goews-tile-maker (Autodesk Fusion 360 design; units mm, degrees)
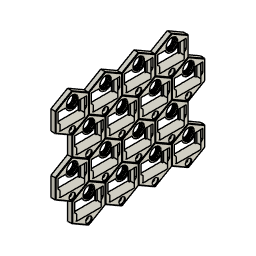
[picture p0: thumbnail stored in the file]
parameter "width" = 42
parameter "height" = 48.497
parameter "offset" = 36.373
parameter "DoubleVerticalDistance" = 72.746
sketch "Reference" plane through (0, 0, 0) normal (1, 0, 0) x axis (0, 1, 0)
  line L1 (-18, -1.6244) -> (-15.5, -4.1244)
  line L2 (-18, 9.8756) -> (-18, -1.6244)
  line L3 (-8.5448, 9.8756) -> (-18, 9.8756)
  line L4 (18, 9.8756) -> (8.5448, 9.8756)
  line L5 (18, -1.6244) -> (18, 9.8756)
  line L6 (15.5, -4.1244) -> (18, -1.6244)
  line L7 (15.5, -12.1244) -> (15.5, -4.1244)
  line L8 (-15.5, -12.1244) -> (15.5, -12.1244)
  line L9 (-15.5, -4.1244) -> (-15.5, -12.1244)
  line L10 (20.5, 11.8357) -> (20.5, -11.8357)
  line L11 (0, 23.6714) -> (20.5, 11.8357)
  line L12 (-20.5, 11.8357) -> (0, 23.6714)
  line L13 (-20.5, -11.8357) -> (-20.5, 11.8357)
  line L14 (0, -23.6714) -> (-20.5, -11.8357)
  line L15 (20.5, -11.8357) -> (0, -23.6714)
  circle C1 centre (0, 12.7017) radius 7.1612
  arc A1 centre (0, 12.7017) radius 9 clockwise from (8.5448, 9.8756) to (-8.5448, 9.8756)
  circle C2 centre (0, -18.2487) radius 4
  point P22 (-42, 24.2487)
  point P27 (-21, -12.1244)
  point P20 (0, -24.2487)
  point P23 (-21, 60.6218)
  point P21 (21, -12.1244)
  point P25 (0, 48.4974)
  point P28 (0, 24.2487)
  point P26 (21, 12.1244)
  dimension "d7" distance P22 P27 = 36.3731
  dimension "d8" distance P20 P23 = 84.8705
  dimension "d9" distance P21 P23 = 84
  dimension "d10" distance P21 P22 = 63
  dimension "d11" distance P20 P25 = 72.7461
  dimension "d17" distance P21 P27 = 42
  dimension "d18" distance P20 P28 = 48.4974
  dimension "d19" distance P23 P28 = 36.3731
  dimension "d24" distance P20 P26 = 36.3731
copy_paste_bodies "CutPasteBodies"
sketch "patch" plane through (-6, 0, 0) normal (-1, 0, 0) x axis (0, -1, 0)
  line L1 (3, 25.9808) -> (16.0118, 18.4684)
  line L2 (3, 26.0061) -> (3, 25.9808)
  line L3 (39, 26.0061) -> (3, 26.0061)
  line L4 (39, 25.9808) -> (39, 26.0061)
  line L5 (25.9882, 18.4684) -> (39, 25.9808)
  curve K1 (16.3334, 53.0977) -> (19.1178, 42.0472)
  curve K2 (22.8822, 42.0472) -> (25.6666, 53.0977)
  line L6 (0, 24.2487) -> (0, 48.4974)
  line L7 (21, 12.1244) -> (0, 24.2487)
  line L8 (42, 24.2487) -> (21, 12.1244)
  line L9 (42, 48.4974) -> (42, 24.2487)
  line L10 (21, 60.6218) -> (42, 48.4974)
  line L11 (0, 48.4974) -> (21, 60.6218)
  line L12 (7.5, 46.2487) -> (7.5, 30.2487)
  line L13 (12.4552, 46.2487) -> (7.5, 46.2487)
  line L14 (34.5, 46.2487) -> (29.5448, 46.2487)
  line L15 (34.5, 30.2487) -> (34.5, 46.2487)
  line L16 (7.5, 30.2487) -> (34.5, 30.2487)
  line L17 (9.8586, 52.0614) -> (11.841, 52.0614)
  line L18 (9.8586, 48.8529) -> (9.8586, 52.0614)
  line L19 (11.841, 48.8529) -> (9.8586, 48.8529)
  line L20 (11.841, 52.0614) -> (11.841, 48.8529)
  line L21 (32.2218, 52.0614) -> (29.7148, 52.0614)
  line L22 (32.2218, 48.4173) -> (32.2218, 52.0614)
  line L23 (29.7148, 48.4173) -> (32.2218, 48.4173)
  line L24 (29.7148, 52.0614) -> (29.7148, 48.4173)
  arc A1 centre (21, 18.1244) radius 5 clockwise from (16.0118, 18.4684) to (25.9882, 18.4684)
  arc A2 centre (21, 49.0748) radius 6.1612 clockwise from (16.3334, 53.0977) to (25.6666, 53.0977)
  arc A3 centre (21, 49.0748) radius 7.2753 clockwise from (22.8822, 42.0472) to (19.1178, 42.0472)
  circle C1 centre (21, 18.1244) radius 2
  arc A4 centre (21, 49.0748) radius 9 clockwise from (29.5448, 46.2487) to (12.4552, 46.2487)
  horizontal L17
  vertical L18
  horizontal L19
  vertical L20
  horizontal L21
  vertical L22
  horizontal L23
  vertical L24
extrude "Extrude1" add sketch "patch" profile of L17 L18 L19 L20 L21 L22 L23 L24 against normal blind 6
copy_paste_bodies "CopyPasteBodies3"
copy_paste_bodies "CopyPasteBodies4"
move "Move3"
align "Align1"
move "Move2"
combine "Combine3" bodies "Hex (1)"
rectangular_pattern "R-Pattern3" countU 2 (= "VerticalQTY / 2") uSpaceDistance 72.746 vSpaceDistance -42 bodies "Hex (1)", "Hex (8)", "Hex (2)", "Hex (3)", "Hex (4)", "Hex (5)", "Hex (6)"
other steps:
base_feature "Base Feature1" bodies "Hex"
base_feature "Base Feature3" bodies "Hex (1)"
base_feature "Base Feature4" bodies "Hex (1) (1)"
named bodies: "Hex", "Hex (1)", "Hex (8)", "Hex (1) (1)", "Hex (3)", "Hex (5)", "Hex (2)", "Hex (4)", "Hex (6)"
